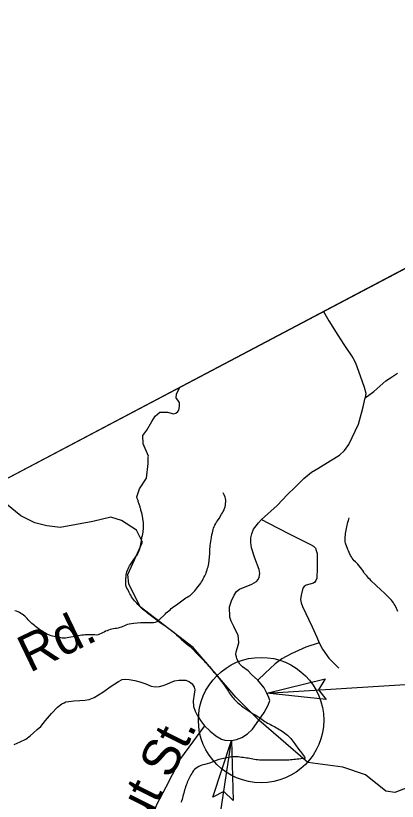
# Model space of a CAD drawing. Extents: x 1379448 to 1382868, y 593769 to 596827.
# Drawn here: x 1379823.8 to 1379976, y 595600.1 to 595913.3 of the extents above; entities that cross this region are included whole.
import ezdxf

# ---------------------------------------------------------------- set-up
doc = ezdxf.new("R2010")
doc.units = 0
for name, color, linetype in [('CTL Sheet Border CELL', 7, 'Continuous'), ('Old_Level_1', 7, 'Continuous'), ('Old_Level_11', 7, 'Continuous'), ('Old_Level_31', 7, 'Continuous'), ('Old_Level_32', 7, 'Continuous'), ('Old_Level_35', 7, 'Continuous'), ('Old_Level_50', 7, 'Continuous'), ('Old_Level_59', 7, 'Continuous'), ('Old_Level_62', 7, 'Continuous'), ('Pattern 1', 7, 'Continuous'), ('Typical Terminator CELL', 7, 'Continuous')]:
    doc.layers.add(name, color=color, linetype=linetype)

msp = doc.modelspace()

# ---------------------------------------------------------------- linework, layer by layer
at = {"layer": 'CTL Sheet Border CELL'}
msp.add_lwpolyline([(1381803.77, 596774.44), (1379496.12, 595557.87), (1380347.71, 593942.52), (1382655.37, 595159.09)], close=True, dxfattribs=at)
at = {"layer": 'Old_Level_1'}
msp.add_line((1379496.12, 595557.87), (1380161.32, 595908.56), dxfattribs=at)
at = {"layer": 'Old_Level_11'}
for p, q in [((1379924.01, 595643.23), (1380010.99, 595648.67)), ((1379894.75, 595523.47), (1379909.86, 595624.29))]:
    msp.add_line(p, q, dxfattribs=at)
at = {"layer": 'Old_Level_31'}
msp.add_line((1379922.62, 595633.44), (1379922.62, 595633.44), dxfattribs=at)
at = {"layer": 'Old_Level_32'}
for points in [[(1379946.58, 595795.35), (1379948.78, 595791.68), (1379952.36, 595785.89), (1379954.67, 595782.27), (1379958.28, 595776.98), (1379959.36, 595774.94), (1379961.16, 595769.79), (1379962.85, 595765.24), (1379963.48, 595762.82), (1379963.19, 595760.95)], [(1379963.19, 595760.95), (1379966.64, 595763.44), (1379971.5, 595767.73), (1379973.33, 595768.93), (1379976.07, 595770.85)], [(1379921.8, 595712.39), (1379928.15, 595718.06), (1379932.18, 595722.43), (1379935.29, 595725.38), (1379938.77, 595728.77), (1379941.77, 595731.27), (1379944.38, 595732.82), (1379949.31, 595735.81), (1379952.92, 595738.06), (1379954.92, 595739.98), (1379956.76, 595742.33), (1379960.54, 595750.43), (1379961.69, 595754.81), (1379962.47, 595757.33), (1379963.19, 595760.95)], [(1379920.43, 595648.34), (1379917.89, 595650.65), (1379916.53, 595652.11), (1379914.31, 595653.66), (1379913.23, 595654.81), (1379912.52, 595655.93), (1379912, 595656.92), (1379911.83, 595657.69), (1379911.66, 595658.58), (1379911.77, 595659.72), (1379912.28, 595661.43), (1379912.85, 595663.28), (1379912.67, 595664.97), (1379912.59, 595666.24), (1379910.79, 595669.77), (1379909.74, 595671.86), (1379909.29, 595673.51), (1379909.14, 595677.6), (1379909.83, 595680), (1379910.97, 595682.32), (1379911.84, 595683.7), (1379913.04, 595684.67), (1379918, 595686.69), (1379919.83, 595687.7), (1379920.59, 595688.54), (1379920.95, 595689.42), (1379921.19, 595690.98), (1379920.98, 595692.57), (1379919.19, 595697.04), (1379917.91, 595701.13), (1379917.57, 595703.24), (1379917.62, 595705.16), (1379917.98, 595706.73), (1379918.7, 595708.61), (1379919.69, 595709.98), (1379920.69, 595711.17), (1379921.8, 595712.39)], [(1379921.8, 595712.39), (1379924.63, 595711.04), (1379932.6, 595706.92), (1379941.44, 595702.51), (1379942.58, 595701.79), (1379943.36, 595701), (1379943.73, 595700.16), (1379944.12, 595698.88), (1379944.09, 595696.8), (1379944.06, 595693.05), (1379943.93, 595689.02), (1379943.59, 595688.1), (1379943.16, 595687.46), (1379942.63, 595687.13), (1379941.12, 595686.73), (1379939.63, 595686.3), (1379938.85, 595685.77), (1379938.32, 595685.09), (1379937.73, 595682.23)], [(1379937.73, 595682.23), (1379937.38, 595680.57), (1379937.65, 595679.28), (1379938.18, 595677.72), (1379942.07, 595669.67), (1379943.97, 595665.51), (1379944.8, 595663.25), (1379939.57, 595661.51), (1379933.63, 595658.9), (1379929.95, 595656.96), (1379927.34, 595654.85), (1379923.33, 595651.23), (1379920.43, 595648.34)], [(1379823.23, 595622.8), (1379825.56, 595623.75), (1379827.81, 595624.88), (1379829.52, 595626.24), (1379830.95, 595627.34), (1379832.38, 595628.66), (1379833.78, 595629.92), (1379835.67, 595632.29), (1379838.09, 595635.11), (1379840.43, 595637.61), (1379842.26, 595638.98), (1379843.1, 595639.42), (1379843.74, 595639.76), (1379844.95, 595639.94), (1379847.02, 595640.17), (1379849.39, 595640.27), (1379851.32, 595640.43), (1379853.08, 595640.67), (1379855.12, 595641.51), (1379858.54, 595643.55), (1379861.89, 595646.06), (1379864.83, 595647.89), (1379866.29, 595648.6), (1379867.59, 595648.83), (1379869.08, 595648.7), (1379871.31, 595648.27), (1379873.27, 595647.69), (1379875.72, 595646.98), (1379877.87, 595646.04), (1379879.57, 595645.73), (1379881.17, 595645.83), (1379882.57, 595646.22), (1379884.03, 595646.82), (1379885.55, 595647.51), (1379887.13, 595648.11), (1379888.87, 595648.4), (1379890.57, 595648.44), (1379891.73, 595648.36), (1379893.2, 595647.7), (1379894.14, 595646.93), (1379894.63, 595646.33), (1379895.04, 595645.57), (1379895.21, 595644.57), (1379895.04, 595642.87), (1379894.62, 595640.18), (1379894.76, 595637.9), (1379895.38, 595636.05), (1379896.19, 595634.41), (1379897.56, 595632.26), (1379899.06, 595630.19)], [(1379920.78, 595632.39), (1379922.94, 595635.49), (1379924.5, 595638.37), (1379925.13, 595640.31), (1379924.73, 595641.42), (1379924.01, 595643.23), (1379922.9, 595645.34), (1379920.43, 595648.34)], [(1379899.06, 595630.19), (1379901.38, 595628.06), (1379903.67, 595626.17), (1379905.95, 595624.86), (1379907.23, 595624.45), (1379909.86, 595624.29), (1379911.9, 595624.79), (1379914.08, 595625.48), (1379916.26, 595626.97), (1379918.31, 595628.91), (1379920.78, 595632.39)], [(1379899.06, 595630.19), (1379889.58, 595617.21), (1379886.27, 595610.7), (1379883.76, 595605.7), (1379879.92, 595598.7), (1379877.96, 595593.17), (1379875.58, 595586.55)]]:
    msp.add_lwpolyline(points, dxfattribs=at)
at = {"layer": 'Old_Level_35'}
msp.add_lwpolyline([(1379944.8, 595663.25), (1379946.23, 595660.73), (1379948.7, 595657.23), (1379952.68, 595653.23)], dxfattribs=at)
at = {"layer": 'Old_Level_50'}
msp.add_line((1379920.83, 595632.4), (1379920.83, 595632.4), dxfattribs=at)
at = {"layer": 'Old_Level_59'}
for points in [[(1379865.99, 595712.11), (1379861.75, 595713.33), (1379854.56, 595711.67), (1379841.54, 595709.31), (1379836.17, 595709.93), (1379831.38, 595711.1), (1379825.8, 595713.98), (1379820.15, 595718.63), (1379814.61, 595725.77)], [(1380029.06, 595612.69), (1380024.72, 595612.43), (1380010.13, 595606.57), (1380003.24, 595606.94), (1379994.91, 595609.37), (1379988.23, 595608.66), (1379975.1, 595603.54), (1379971.47, 595604.07), (1379963.32, 595610.7), (1379954.37, 595613.7), (1379940.34, 595615.62), (1379920.78, 595632.39), (1379911.66, 595641.62), (1379894.65, 595661.43), (1379873.48, 595677.68), (1379868.88, 595686.83), (1379868.53, 595690.48), (1379874.38, 595703.4), (1379871.94, 595708.2), (1379865.99, 595712.11)]]:
    msp.add_lwpolyline(points, dxfattribs=at)
at = {"layer": 'Old_Level_62'}
for points in [[(1379873.88, 595715.78), (1379873.72, 595716.24), (1379873.72, 595716.6), (1379873.43, 595717.17), (1379873.43, 595717.52), (1379872.72, 595719.67), (1379872.72, 595720.03), (1379872.29, 595720.88), (1379872.15, 595721.52), (1379873.22, 595724.74), (1379875.94, 595728.96), (1379876.59, 595734.82), (1379876.59, 595737.32), (1379876.73, 595737.75), (1379874.59, 595742.67), (1379874.46, 595745.92), (1379876.07, 595748.06), (1379878.16, 595751.47), (1379879.42, 595753.72), (1379881.32, 595755.3), (1379884.41, 595755.2), (1379886.75, 595754.54), (1379887.65, 595754.9), (1379888.43, 595755.47), (1379888.86, 595756.04), (1379889.19, 595757.54), (1379889.19, 595758.97), (1379889.05, 595759.26), (1379887.87, 595760.92), (1379887.95, 595762.4), (1379889.04, 595764.71), (1379889.4, 595765.2)], [(1379880.64, 595671.98), (1379881.07, 595672.47), (1379883.41, 595674.75), (1379883.88, 595675.2), (1379884.38, 595675.64), (1379884.87, 595676.08), (1379885.37, 595676.5), (1379885.87, 595676.92), (1379886.39, 595677.33), (1379888.47, 595678.89), (1379891.1, 595680.84), (1379891.65, 595681.21), (1379892.23, 595681.52), (1379892.82, 595681.82), (1379893.36, 595682.18), (1379893.86, 595682.6), (1379894.33, 595683.05), (1379894.79, 595683.52), (1379895.24, 595684.02), (1379895.67, 595684.51), (1379896.09, 595685.02), (1379897.63, 595687.04), (1379897.95, 595687.61), (1379898.27, 595688.18), (1379898.59, 595688.76), (1379898.9, 595689.34), (1379899.2, 595689.93), (1379899.49, 595690.52), (1379899.75, 595691.12), (1379899.98, 595691.74), (1379900.19, 595692.36), (1379900.37, 595692.99), (1379900.55, 595693.62), (1379900.68, 595694.26), (1379900.79, 595694.92), (1379901.22, 595698.83), (1379901.28, 595700.13), (1379901.41, 595702.08), (1379901.85, 595705.33), (1379902.1, 595706.49), (1379902.26, 595707.12), (1379902.4, 595707.77), (1379902.57, 595708.41), (1379902.77, 595709.03), (1379903.02, 595709.64), (1379903.31, 595710.22), (1379903.63, 595710.8), (1379903.95, 595711.37), (1379904.3, 595711.93), (1379904.92, 595712.88), (1379905.96, 595714.56), (1379906.3, 595715.12), (1379906.62, 595715.69), (1379906.92, 595716.28), (1379907.14, 595716.89), (1379907.3, 595717.53), (1379907.44, 595718.17), (1379907.56, 595718.82), (1379907.61, 595719.47), (1379907.6, 595720.13), (1379907.53, 595720.79), (1379907.36, 595721.42), (1379907.11, 595722.02), (1379906.55, 595723.13)], [(1379874.13, 595704.84), (1379874.12, 595705.47), (1379874.35, 595706.08), (1379874.48, 595706.72), (1379874.59, 595707.36), (1379874.68, 595707.99), (1379874.75, 595708.62), (1379874.81, 595709.24), (1379874.84, 595709.86), (1379874.85, 595710.48), (1379874.79, 595711.11), (1379874.55, 595712.91), (1379874.23, 595714.57), (1379873.88, 595715.78)], [(1379976.28, 595675.78), (1379976, 595676.38), (1379975.72, 595676.98), (1379975.44, 595677.58), (1379975.15, 595678.17), (1379974.83, 595678.74), (1379974.49, 595679.29), (1379974.11, 595679.82), (1379973.68, 595680.31), (1379973.22, 595680.77), (1379970.88, 595683.08), (1379969.44, 595684.42), (1379965.64, 595688.03), (1379965.17, 595688.49), (1379964.72, 595688.97), (1379964.28, 595689.45), (1379963.84, 595689.94), (1379963.42, 595690.45), (1379963, 595690.95), (1379962.62, 595691.49), (1379962.3, 595692.06), (1379961.92, 595692.6), (1379960.34, 595694.66), (1379959.87, 595695.11), (1379959.37, 595695.54), (1379958.89, 595696), (1379958.44, 595696.48), (1379958.07, 595697.01), (1379957.73, 595697.57), (1379957.43, 595698.16), (1379956.82, 595699.32), (1379956.52, 595699.91), (1379956.26, 595700.51), (1379955.38, 595702.98), (1379955.27, 595703.61), (1379955.24, 595704.27), (1379955.24, 595704.93), (1379955.28, 595705.59), (1379955.33, 595706.24), (1379955.41, 595706.9), (1379955.5, 595707.55), (1379955.61, 595708.2), (1379955.72, 595708.84), (1379955.86, 595709.49), (1379956, 595710.13), (1379956.16, 595710.76), (1379956.36, 595711.39), (1379956.59, 595712.01), (1379956.8, 595713.17)], [(1379880.64, 595671.98), (1379880.11, 595672.38), (1379879.59, 595672.77), (1379879.06, 595673.17), (1379878.54, 595673.56), (1379878.01, 595673.96), (1379877.49, 595674.35), (1379876.96, 595674.75), (1379876.44, 595675.14), (1379875.92, 595675.54), (1379875.4, 595675.94), (1379874.88, 595676.34), (1379874.37, 595676.76), (1379872.51, 595678.59), (1379872.08, 595679.08), (1379871.65, 595679.58), (1379871.23, 595680.08), (1379870.83, 595680.6), (1379870.43, 595681.12), (1379870.05, 595681.65), (1379869.71, 595682.22), (1379869.39, 595682.79), (1379869.09, 595683.37), (1379868.78, 595683.96), (1379868.48, 595684.54), (1379868.2, 595685.14), (1379867.94, 595685.74), (1379867.75, 595686.37), (1379867.68, 595687.02), (1379867.68, 595687.68), (1379867.7, 595688.33), (1379867.75, 595688.99), (1379867.81, 595689.65), (1379867.9, 595690.3), (1379868.03, 595690.94), (1379868.2, 595691.57), (1379868.4, 595692.2), (1379868.64, 595692.82), (1379868.9, 595693.41), (1379869.2, 595694), (1379869.54, 595694.57), (1379870.66, 595696.17), (1379871.81, 595697.77), (1379872.2, 595698.29), (1379872.54, 595698.85), (1379872.84, 595699.44), (1379873.11, 595700.04), (1379873.32, 595700.66), (1379873.5, 595701.29), (1379873.65, 595701.94), (1379873.78, 595702.58), (1379873.88, 595703.22), (1379874.13, 595704.84)], [(1379880.64, 595671.98), (1379880.05, 595671.68), (1379879.45, 595671.4), (1379878.81, 595671.3), (1379878.15, 595671.29), (1379877.49, 595671.28), (1379876.84, 595671.28), (1379876.18, 595671.27), (1379875.52, 595671.27), (1379874.86, 595671.26), (1379874.21, 595671.25), (1379873.56, 595671.24), (1379870.96, 595671.04), (1379869.04, 595670.69), (1379868.4, 595670.56), (1379867.78, 595670.35), (1379867.17, 595670.11), (1379866.57, 595669.84), (1379865.96, 595669.58), (1379865.35, 595669.34), (1379864.72, 595669.15), (1379864.08, 595669.03), (1379863.42, 595668.95), (1379862.76, 595668.88), (1379862.11, 595668.78), (1379861.49, 595668.61), (1379860.87, 595668.38), (1379860.26, 595668.13), (1379859.66, 595667.87), (1379859.06, 595667.59), (1379858.46, 595667.31), (1379857.86, 595667.03), (1379857.26, 595666.77), (1379856.66, 595666.52), (1379856.05, 595666.39), (1379855.4, 595666.52), (1379854.74, 595666.52), (1379854.09, 595666.53), (1379853.43, 595666.52), (1379852.77, 595666.51), (1379852.11, 595666.49), (1379851.46, 595666.44), (1379850.81, 595666.39), (1379850.16, 595666.3), (1379849.51, 595666.17), (1379848.87, 595666.02), (1379848.23, 595665.88), (1379847.59, 595665.74), (1379845.01, 595665.37), (1379844.36, 595665.28), (1379843.7, 595665.2), (1379843.05, 595665.16), (1379842.4, 595665.16), (1379841.75, 595665.24), (1379841.1, 595665.38), (1379838.53, 595665.96), (1379837.9, 595666.13), (1379837.27, 595666.34), (1379836.68, 595666.6), (1379836.11, 595666.93), (1379833.87, 595668.25), (1379833.34, 595668.64), (1379832.81, 595669.03), (1379832.29, 595669.43), (1379831.77, 595669.82), (1379831.25, 595670.23), (1379830.73, 595670.63), (1379830.22, 595671.05), (1379829.73, 595671.48), (1379829.25, 595671.94), (1379828.81, 595672.42), (1379828.38, 595672.92), (1379827.94, 595673.41), (1379827.47, 595673.86), (1379826.95, 595674.26), (1379826.42, 595674.65), (1379825.88, 595675.02), (1379825.33, 595675.39), (1379824.74, 595675.68), (1379824.11, 595675.87), (1379823.46, 595676.03)], [(1379880.64, 595671.98), (1379881.69, 595671.2), (1379883.87, 595669.74), (1379884.42, 595669.39), (1379884.95, 595669.01), (1379885.48, 595668.61), (1379886, 595668.22), (1379886.52, 595667.82), (1379887.04, 595667.41), (1379887.96, 595666.52), (1379888.88, 595665.62), (1379889.86, 595664.75), (1379891.82, 595663.06), (1379893.34, 595661.8), (1379893.84, 595661.37), (1379896.56, 595658.56), (1379898.84, 595656.2), (1379899.29, 595655.73), (1379899.74, 595655.25), (1379900.19, 595654.77), (1379900.62, 595654.28), (1379901.06, 595653.79), (1379901.49, 595653.29), (1379901.92, 595652.79), (1379902.34, 595652.29), (1379902.76, 595651.78), (1379903.18, 595651.28), (1379903.59, 595650.77), (1379906.77, 595646.62), (1379907.91, 595645.03), (1379908.28, 595644.49), (1379908.65, 595643.94), (1379909.01, 595643.4), (1379909.39, 595642.86), (1379909.78, 595642.33), (1379910.18, 595641.81), (1379910.59, 595641.3), (1379911.02, 595640.8), (1379911.47, 595640.32), (1379911.94, 595639.86), (1379912.41, 595639.41), (1379912.91, 595638.98), (1379913.42, 595638.57), (1379913.94, 595638.17), (1379914.47, 595637.78), (1379915, 595637.39), (1379916.6, 595636.24), (1379917.14, 595635.87), (1379917.69, 595635.51), (1379918.25, 595635.16), (1379918.82, 595634.83), (1379919.39, 595634.51), (1379919.96, 595634.18), (1379920.51, 595633.83), (1379921.06, 595633.46), (1379921.6, 595633.09), (1379922.13, 595632.71), (1379922.67, 595632.33), (1379923.21, 595631.96), (1379923.76, 595631.6), (1379924.32, 595631.27), (1379924.92, 595630.98), (1379925.51, 595630.7), (1379926.08, 595630.38), (1379926.66, 595630.06), (1379927.22, 595629.73), (1379927.8, 595629.41), (1379928.36, 595629.08), (1379928.93, 595628.74), (1379929.48, 595628.4), (1379930.04, 595628.04), (1379930.59, 595627.68), (1379931.13, 595627.31), (1379931.65, 595626.91), (1379932.17, 595626.5), (1379932.64, 595626.05), (1379933.1, 595625.58), (1379933.54, 595625.09), (1379933.96, 595624.59), (1379934.37, 595624.08), (1379934.78, 595623.56), (1379935.18, 595623.04), (1379936.66, 595620.93), (1379937.44, 595619.9), (1379938.61, 595618.37), (1379938.96, 595617.82), (1379939.33, 595617.23)], [(1379939.33, 595617.23), (1379936.71, 595616.92), (1379936.06, 595616.85), (1379935.41, 595616.78), (1379934.76, 595616.71), (1379934.11, 595616.65), (1379933.45, 595616.59), (1379932.8, 595616.56), (1379932.14, 595616.54), (1379927.56, 595616.43), (1379926.91, 595616.48), (1379926.26, 595616.5), (1379925.6, 595616.51), (1379924.94, 595616.5), (1379924.29, 595616.5), (1379923.63, 595616.5), (1379922.97, 595616.49), (1379922.31, 595616.5), (1379921.66, 595616.52), (1379921, 595616.54), (1379920.35, 595616.59), (1379919.69, 595616.66), (1379919.05, 595616.73), (1379918.44, 595616.91), (1379917.79, 595617.02), (1379917.14, 595617.12), (1379916.49, 595617.23), (1379915.85, 595617.33), (1379915.19, 595617.43), (1379914.55, 595617.53), (1379913.89, 595617.62), (1379913.24, 595617.7), (1379912.59, 595617.77), (1379911.94, 595617.81), (1379911.28, 595617.81), (1379910.62, 595617.79), (1379909.97, 595617.76), (1379909.31, 595617.71), (1379908.66, 595617.59), (1379908.02, 595617.47), (1379907.38, 595617.34), (1379906.73, 595617.21), (1379906.09, 595617.06), (1379905.45, 595616.91), (1379904.82, 595616.73), (1379901.16, 595615.35), (1379899.28, 595614.79), (1379898.63, 595614.64), (1379898, 595614.45), (1379897.4, 595614.2), (1379896.8, 595613.91), (1379896.22, 595613.59), (1379895.68, 595613.21), (1379895.18, 595612.79), (1379894.76, 595612.31), (1379894.38, 595611.77), (1379894.02, 595611.21), (1379893.68, 595610.64), (1379892.27, 595607.71), (1379892.02, 595607.1), (1379891.79, 595606.48), (1379891.58, 595605.86), (1379891.38, 595605.24), (1379891.18, 595604.61), (1379890.99, 595603.98), (1379890.82, 595603.35), (1379890.67, 595602.71), (1379890.52, 595602.07), (1379890.35, 595601.44), (1379890.16, 595600.81), (1379889.94, 595600.19), (1379889.72, 595599.57)]]:
    msp.add_lwpolyline(points, dxfattribs=at)
at = {"layer": 'Pattern 1'}
msp.add_circle((1379921.68, 595632.48), 25, dxfattribs=at)
at = {"layer": 'Typical Terminator CELL'}
for points in [[(1379947.65, 595640.66), (1379924.01, 595643.23), (1379947.27, 595648.86), (1379944.54, 595644.51)], [(1379902.42, 595601.7), (1379909.86, 595624.29), (1379910.51, 595600.37), (1379906.83, 595603.94)]]:
    msp.add_lwpolyline(points, close=True, dxfattribs=at)

# ---------------------------------------------------------------- texts
at = {"layer": 'Old_Level_11'}
for s, height, rotation, p in [('Rd.', 14.764, 25.7325, (1379829.36, 595651.2)), ('St.', 14.764, 63.3136, (1379885.59, 595608.58)), ('BEGIN PROJECT', 14, 27.7977, (1379900.85, 595529.45)), ('Chestnut', 14.764, 63.3136, (1379847.28, 595533.22))]:
    msp.add_text(s, height=height, rotation=rotation, dxfattribs=at).set_placement(p)

doc.saveas('drawing.dxf')
